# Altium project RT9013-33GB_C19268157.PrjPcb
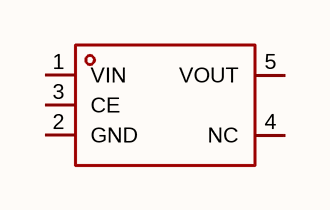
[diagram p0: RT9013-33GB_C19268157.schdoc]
1 sheet, 1 parts. Net scope: global (net labels, ports and power ports of the same name join across sheets).

## Sheet RT9013-33GB_C19268157.schdoc
size 127 x 101 mm

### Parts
U?  rt9013-33gb_c19268157  [SOT-23-5_L2.9-W1.6-P0.95-LS2.8-BR]  (value not drawn)

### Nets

Not connected (* = marked no-connect by the designer): U? 1(VIN) 2(GND) 3(CE) 4(NC) 5(VOUT)

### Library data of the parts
U? = rt9013-33gb_c19268157: 输出极性:正极;工作电压:7V;输出电压:3.3V;输出电流:500mA;电源纹波抑制比(PSRR):70dB@(1kHz);输出类型:固定;; Manufacturer: TECH PUBLIC(台舟); AddInBom: yes; ModelId: 7ba65df16e7b4570af156e925f9c37fe; ModelTransform: 114.173,114.173,0,90,0,0,0,0,0; Output Configuration: 正极; Voltage - Supply: 7V; Output Voltage: 3.3V; Output Current: 500mA; Voltage Dropout: 100mV@(100mA)；300mV@(200mA); standby current: 60uA; Noise: 50uVrms; Output Type: 固定; Number of Outputs: 1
